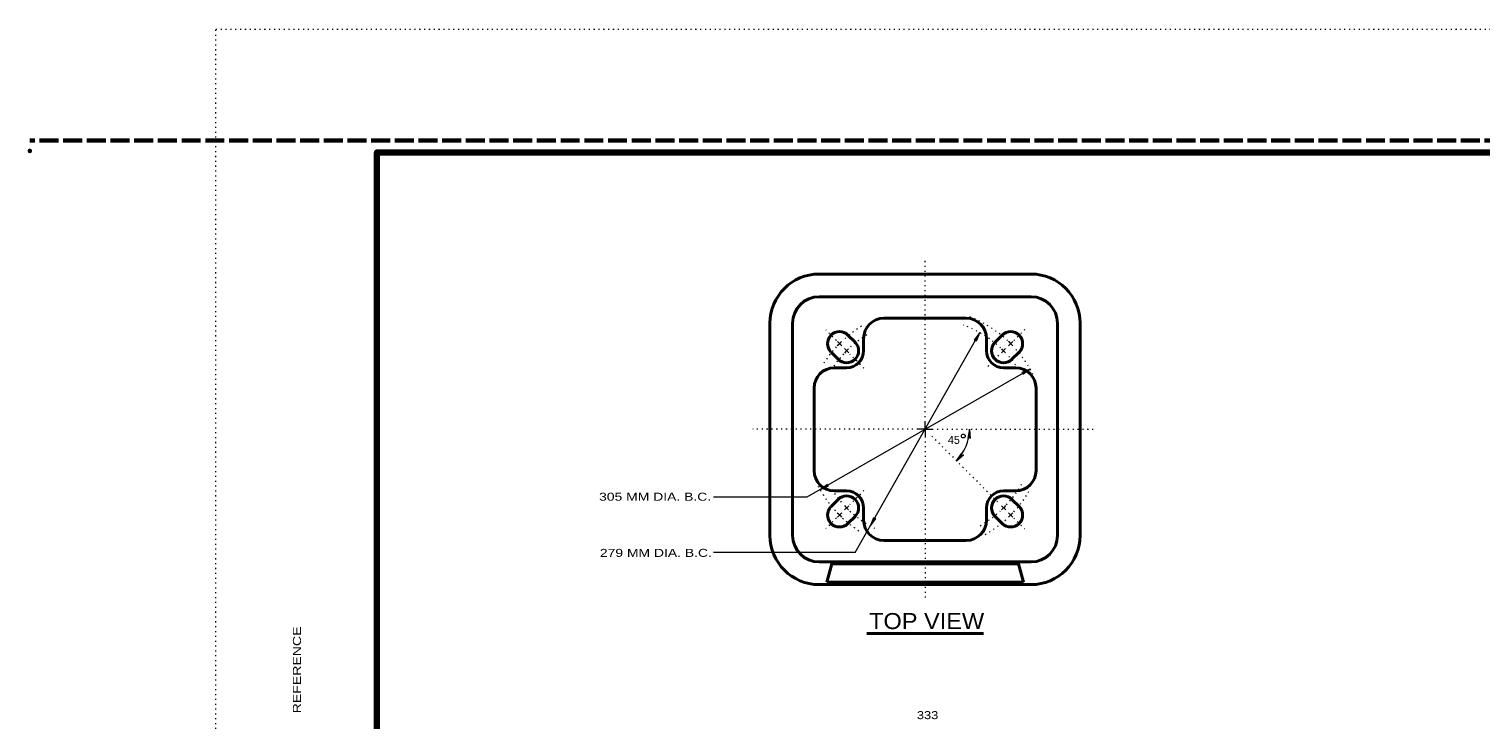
# Model space of a CAD drawing. Extents: x 312583 to 312854, y 144419 to 144597.
# Drawn here: x 312583.5 to 312721.4, y 144531.2 to 144596.8 of the extents above; entities that cross this region are included whole.
import ezdxf
from ezdxf.enums import TextEntityAlignment as Align

# ---------------------------------------------------------------- set-up
doc = ezdxf.new("R2010")
doc.units = 0
doc.header["$LTSCALE"] = 0.3
doc.header["$PDMODE"] = 32
doc.header["$PDSIZE"] = 0.15
doc.linetypes.add('DOTTED', pattern=[1.5, 0.3, -1.2])
doc.linetypes.add('LONG_DASHED', pattern=[7.5, 6, -1.5])
for name, color, linetype, lineweight in [('1', 7, 'Continuous', 40), ('2', 7, 'Continuous', 13), ('62', 7, 'DOTTED', 13), ('63', 7, 'LONG_DASHED', 60)]:
    doc.layers.add(name, color=color, linetype=linetype, lineweight=lineweight)

msp = doc.modelspace()

# ---------------------------------------------------------------- linework, layer by layer
at = {"layer": '1'}
for p, q in [((312658.5044, 144573.5356), (312668.5631, 144573.5356)), ((312678.6294, 144573.5356), (312668.5631, 144573.5356)), ((312658.5044, 144571.3812), (312668.5631, 144571.3812)), ((312678.6294, 144571.3812), (312668.5631, 144571.3812)), ((312668.5631, 144569.3496), (312664.6454, 144569.3496)), ((312672.4807, 144569.3496), (312668.5631, 144569.3496)), ((312653.8277, 144568.8666), (312653.8277, 144558.8079)), ((312655.9821, 144568.8666), (312655.9821, 144558.8079)), ((312661.9161, 144567.0649), (312661.2414, 144567.7396)), ((312675.2101, 144567.0649), (312675.8924, 144567.7396)), ((312681.1441, 144568.8666), (312681.1441, 144558.8079)), ((312683.2984, 144568.8666), (312683.2984, 144558.8079)), ((312662.7287, 144567.4329), (312662.7287, 144566.2599)), ((312674.3974, 144567.4329), (312674.3974, 144566.2599)), ((312660.3061, 144565.4549), (312659.6314, 144566.1296)), ((312676.8201, 144565.4549), (312677.5024, 144566.1296)), ((312659.9381, 144564.6422), (312661.1111, 144564.6422)), ((312677.1881, 144564.6422), (312676.0151, 144564.6422)), ((312658.0214, 144562.7256), (312658.0214, 144558.8079)), ((312679.1047, 144558.8079), (312679.1047, 144562.7256)), ((312653.8277, 144548.7416), (312653.8277, 144558.8079)), ((312655.9821, 144548.7416), (312655.9821, 144558.8079)), ((312658.0214, 144558.8079), (312658.0214, 144554.8826)), ((312679.1047, 144554.8826), (312679.1047, 144558.8079)), ((312681.1441, 144548.7416), (312681.1441, 144558.8079)), ((312683.2984, 144548.7416), (312683.2984, 144558.8079)), ((312659.9381, 144552.9659), (312661.1111, 144552.9659)), ((312677.1881, 144552.9659), (312676.0151, 144552.9659)), ((312660.3061, 144552.1532), (312659.6314, 144551.4786)), ((312662.7287, 144550.1829), (312662.7287, 144551.3482)), ((312674.3974, 144550.1829), (312674.3974, 144551.3482)), ((312676.8201, 144552.1532), (312677.5024, 144551.4786)), ((312661.9161, 144550.5432), (312661.2414, 144549.8686)), ((312675.2101, 144550.5432), (312675.8924, 144549.8686)), ((312664.6454, 144548.2662), (312668.5631, 144548.2662)), ((312668.5631, 144548.2662), (312672.4807, 144548.2662)), ((312658.5044, 144546.2269), (312668.5631, 144546.2269)), ((312678.6294, 144546.2269), (312668.5631, 144546.2269)), ((312668.5631, 144544.3102), (312659.2174, 144544.3102)), ((312668.5631, 144544.3102), (312677.9087, 144544.3102)), ((312658.5044, 144544.0726), (312668.5631, 144544.0726)), ((312678.6294, 144544.0726), (312668.5631, 144544.0726))]:
    msp.add_line(p, q, dxfattribs=at)
at = {"layer": '1', "linetype": 'DOTTED', "lineweight": 13}
for p, q in [((312660.1374, 144567.2336), (312659.1331, 144568.2302)), ((312676.9964, 144567.2336), (312678.1387, 144568.3836)), ((312662.7517, 144564.6116), (312661.4254, 144565.9456)), ((312674.5354, 144564.7802), (312675.7161, 144565.9609)), ((312669.2071, 144558.1639), (312675.7084, 144551.6626)), ((312662.7517, 144552.9966), (312661.4254, 144551.6626)), ((312660.1374, 144550.3746), (312659.1331, 144549.3779)), ((312676.9964, 144550.3746), (312677.9931, 144549.3779))]:
    msp.add_line(p, q, dxfattribs=at)
at = {"layer": '1', "lineweight": 13}
for p, q in [((312660.6434, 144566.7276), (312660.2371, 144567.1339)), ((312661.3104, 144566.0606), (312660.9041, 144566.4592)), ((312675.8081, 144566.0529), (312676.2144, 144566.4592)), ((312676.4827, 144566.7276), (312676.8891, 144567.1339)), ((312661.3104, 144551.5552), (312660.9041, 144551.1489)), ((312675.8157, 144551.5552), (312676.2221, 144551.1489)), ((312660.6434, 144550.8806), (312660.2371, 144550.4742)), ((312676.4827, 144550.8806), (312676.8891, 144550.4742))]:
    msp.add_line(p, q, dxfattribs=at)
at = {"layer": '1', "lineweight": 158}
msp.add_lwpolyline([(312616.5, 144423.1446), (312616.5, 144585.0846), (312849, 144585.0846)], dxfattribs=at)
at = {"layer": '1'}
for points in [[(312668.5631, 144546.0429), (312659.7004, 144546.0429), (312659.2174, 144544.3102)], [(312668.5631, 144546.0429), (312677.4334, 144546.0429), (312677.9087, 144544.3102)]]:
    msp.add_lwpolyline(points, dxfattribs=at)
for centre, radius, start, end in [((312658.5006, 144568.8666), 4.6719, 90, 180), ((312678.6256, 144568.8666), 4.6719, 0, 90), ((312658.5006, 144568.8666), 2.5156, 90, 180), ((312678.6256, 144568.8666), 2.5156, 0, 90), ((312664.6435, 144567.4291), 1.9167, 90, 180), ((312672.4827, 144567.4291), 1.9167, 0, 90), ((312660.4326, 144566.9346), 1.1384, 45, 225), ((312676.6936, 144566.9346), 1.1384, 315, 135), ((312661.1092, 144566.258), 1.1384, 225, 45), ((312676.017, 144566.258), 1.1384, 135, 315), ((312661.1092, 144566.258), 1.6176, 270, 0), ((312676.017, 144566.258), 1.6176, 180, 270), ((312659.9381, 144562.7236), 1.9167, 90, 180), ((312677.1881, 144562.7236), 1.9167, 0, 90), ((312659.9381, 144554.8845), 1.9167, 180, 270), ((312677.1881, 144554.8845), 1.9167, 270, 0), ((312661.1092, 144551.3502), 1.6176, 0, 90), ((312676.017, 144551.3502), 1.6176, 90, 180), ((312660.4326, 144550.6736), 1.1384, 135, 315), ((312661.1092, 144551.3502), 1.1384, 315, 135), ((312676.017, 144551.3502), 1.1384, 45, 225), ((312676.6936, 144550.6736), 1.1384, 225, 45), ((312664.6435, 144550.1791), 1.9167, 180, 270), ((312672.4827, 144550.1791), 1.9167, 270, 0), ((312658.5006, 144548.7416), 4.6719, 180, 270), ((312658.5006, 144548.7416), 2.5156, 180, 270), ((312678.6256, 144548.7416), 4.6719, 270, 0), ((312678.6256, 144548.7416), 2.5156, 270, 0)]:
    msp.add_arc(centre, radius, start, end, dxfattribs=at)
at = {"layer": '1', "linetype": 'DOTTED', "lineweight": 13}
for radius, start, end in [(11.5, 47.09459, 69.71374), (11.5, 121.71451, 132.90639), (10.5417, 121.71386, 132.58339), (10.5419, 47.09821, 69.71374), (11.5, 137.18158, 147.17965), (11.5, 26.95504, 42.81842), (10.5417, 137.23997, 147.17573), (10.5419, 35.43952, 42.71938), (11.5, 207.95114, 222.81842), (10.5417, 212.82427, 222.76003), (10.5417, 317.23939, 330.45291), (11.5, 317.18755, 330.45291), (11.5, 227.09361, 238.28549), (10.5417, 227.41661, 243.86032), (10.5417, 299.81853, 312.58463), (11.5, 299.81853, 312.90541)]:
    msp.add_arc((312668.5631, 144558.8041), radius, start, end, dxfattribs=at)
at = {"layer": '1', "lineweight": 13}
for radius, start, end in [(11.5, 133.65585, 136.45218), (10.5417, 133.51949, 136.65089), (10.5414, 43.54782, 46.34415), (11.5, 43.54782, 46.34415), (10.5417, 223.34911, 226.48051), (10.5417, 313.51949, 316.65089), (11.5, 223.54782, 226.34415), (11.5, 313.65585, 316.45218)]:
    msp.add_arc((312668.5631, 144558.8041), radius, start, end, dxfattribs=at)
at = {"layer": '1'}
msp.add_point((312583.526, 144585.2246), dxfattribs=at)
at = {"layer": '2', "linetype": 'DOTTED'}
for p, q in [((312668.5631, 144559.9579), (312668.5631, 144574.8926)), ((312667.4131, 144558.8079), (312652.2177, 144558.8079)), ((312669.7131, 144558.8079), (312684.7167, 144558.8079)), ((312668.5631, 144557.6579), (312668.5631, 144542.6542))]:
    msp.add_line(p, q, dxfattribs=at)
at = {"layer": '2'}
for p, q in [((312661.9314, 144547.1086), (312673.7611, 144567.9772)), ((312673.7611, 144567.9772), (312673.2397, 144567.2719)), ((312673.7611, 144567.9772), (312673.4314, 144567.1722)), ((312673.2397, 144567.2719), (312673.4697, 144567.4636)), ((312673.4314, 144567.1722), (312673.4697, 144567.4636)), ((312678.5451, 144564.5272), (312657.3314, 144552.3679)), ((312678.5451, 144564.5272), (312677.7401, 144564.1899)), ((312677.7401, 144564.1899), (312678.0314, 144564.2282)), ((312678.5451, 144564.5272), (312677.8474, 144563.9982)), ((312677.8474, 144563.9982), (312678.0314, 144564.2282)), ((312668.5631, 144558.8079), (312668.5631, 144559.5746)), ((312668.5631, 144558.8079), (312668.5631, 144559.5746)), ((312668.5631, 144558.8079), (312667.7964, 144558.8079)), ((312668.5631, 144558.8079), (312669.3297, 144558.8079)), ((312668.5631, 144558.8079), (312668.5631, 144558.0412)), ((312672.7797, 144558.8079), (312672.6264, 144557.9492)), ((312672.6264, 144557.9492), (312672.7491, 144558.2176)), ((312672.8411, 144557.9339), (312672.7491, 144558.2176)), ((312672.7797, 144558.8079), (312672.8411, 144557.9339)), ((312671.5454, 144555.8256), (312672.0437, 144556.5386)), ((312671.5454, 144555.8256), (312672.2047, 144556.3929)), ((312672.0437, 144556.5386), (312671.9364, 144556.2626)), ((312672.2047, 144556.3929), (312671.9364, 144556.2626)), ((312658.5887, 144553.0886), (312659.2864, 144553.6099)), ((312658.5887, 144553.0886), (312659.3937, 144553.4259)), ((312659.2864, 144553.6099), (312659.1024, 144553.3799)), ((312659.3937, 144553.4259), (312659.1024, 144553.3799)), ((312657.3314, 144552.3679), (312648.4687, 144552.3679)), ((312663.3651, 144549.6309), (312663.7024, 144550.4436)), ((312663.3651, 144549.6309), (312663.8864, 144550.3362)), ((312663.7024, 144550.4436), (312663.6564, 144550.1446)), ((312663.8864, 144550.3362), (312663.6564, 144550.1446)), ((312661.9314, 144547.1086), (312648.4687, 144547.1086))]:
    msp.add_line(p, q, dxfattribs=at)
at = {"layer": '2', "lineweight": 40}
msp.add_line((312663.018, 144539.4165), (312674.104, 144539.4165), dxfattribs=at)
at = {"layer": '2'}
msp.add_circle((312672.193, 144558.1638), 0.1797, dxfattribs=at)
msp.add_arc((312668.5631, 144558.8041), 4.2148, 315, 0, dxfattribs=at)
at = {"layer": '62'}
for p, q in [((312601.2, 144596.7846), (312853.5, 144596.7846)), ((312601.2, 144418.5846), (312601.2, 144596.7846))]:
    msp.add_line(p, q, dxfattribs=at)
at = {"layer": '63'}
msp.add_line((312851.75, 144586.2246), (312583.526, 144586.2246), dxfattribs=at)

# ---------------------------------------------------------------- texts
at = {"layer": '1', "width": 1.3}
msp.add_text('REFERENCE                                                              ', height=0.7682, rotation=90, dxfattribs=at).set_placement((312609.2854, 144531.8549))
at = {"layer": '2'}
msp.add_text('45', height=0.76, dxfattribs=at).set_placement((312670.733, 144557.4253))
for s, width, p in [('305 MM DIA. B.C.', 1.3, (312637.5978, 144552.0289)), ('279 MM DIA. B.C.', 1.3, (312637.6721, 144546.6995)), ('333 ', 1.2, (312667.7865, 144531.3028))]:
    msp.add_text(s, height=0.76, dxfattribs=dict(at, width=width)).set_placement(p)
at = {"layer": '2', "width": 1.1}
msp.add_text('TOP VIEW', height=1.52, dxfattribs=at).set_placement((312668.712, 144539.8496), align=Align.CENTER)

doc.saveas('drawing.dxf')
